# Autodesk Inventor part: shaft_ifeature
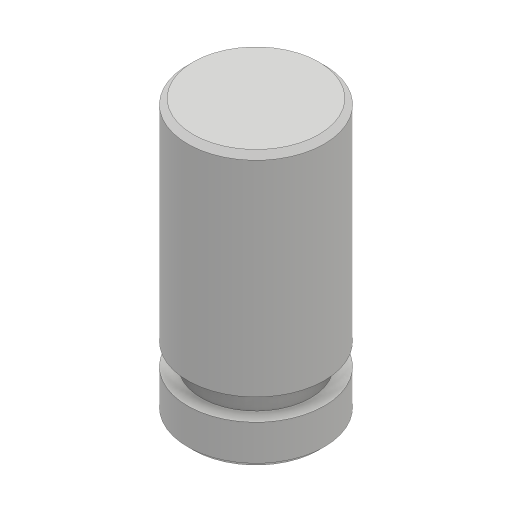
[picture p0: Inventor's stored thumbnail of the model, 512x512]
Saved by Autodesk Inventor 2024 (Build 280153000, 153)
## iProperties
Created: 2016-08
Part Number: shaft_ifeature
Material: Generic
Document SubType Name: Modeling
Designer: Sandeep
Density: 1 g/cm^3
Appearance: Default
Author: Sandeep
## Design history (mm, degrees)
sketch "Sketch1"
  geometry: C1 r 25 at (0, 0); 1 further point
  constraints: 1 centre point, 1 coincident
  dimensions: "d0" = 50 diameter of C1
extrude "Extrusion1" new body sketch "Sketch1" distance "d1" = 100; taper "d2" = 0 deg
chamfer "Chamfer1" distance "d3" = 2; stored, may be unused: second distance "d4" = 2, angle "d5" = 45 deg
chamfer "Chamfer2" distance "d6" = 2; stored, may be unused: second distance "d7" = 2, angle "d8" = 45 deg
sketch "Sketch3"
  geometry: L1 (-25, 23)-(-20, 23); L2 (-20, 23)-(-20, 15); L3 (-20, 15)-(-25, 15); L4 (-25, 15)-(-25, 23); L5 (0, 0)-(0, 35)
  constraints: 10 end point, 2 parallel, 1 horizontal, 1 perpendicular, 1 vertical
  dimensions: "d13" = 8 distance of L3.end L1.start; "d14" = 25 distance between parallel lines of L4 L5; "d15" = 20 distance between parallel lines of L2 L5; "d17" = 15 distance from line of L3 L5.start
revolve "Revolution2" sketch "Sketch3" stored, may be unused: angle "d18" = 90 deg
body "Solid1"
